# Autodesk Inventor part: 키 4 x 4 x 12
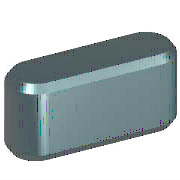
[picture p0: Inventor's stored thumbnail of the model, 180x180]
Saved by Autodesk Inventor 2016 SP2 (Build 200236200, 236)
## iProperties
IsCustomPart: 1
Created: 2012-02
Part Number: 키 4 x 4 x 12
Material: 강철, 연강
Description: 키 및 해당 키홈
Document SubType Name: Modeling
Standard: KS B 1311
Designer: mduedu
Standards Organization: KS
Language: ko-KR
Size Designation: 4 x 4 x 12
Categories: <MemberInstance><Categories><Category DisplayName="샤프트 부품" InternalName="7f7aeb1f-a693-4053-b835-cee3144e0d98" Mnemonic="SHFT"><Category DisplayName="키" Interna
Density: 1 g/cm^3
Appearance: 노란색
Author: mduedu
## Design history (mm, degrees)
workplane "Work Plane1"
workplane "Work Plane2"
sketch "스케치1"
  geometry: L1 (2, 2)-(10, 2); L2 (10, -2)-(2, -2); L3 (0, 9.4)-(0, -7.4) reference; L4 (-5, 0)-(30, 0) reference; L5 (12, 0)-(12, 7); A1 r 2 centre (2, 0) between (2, 2) and (2, -2); A2 r 2 centre (10, 0) between (10, -2) and (10, 2)
  constraints: 6 end point, 5 point on circle, 4 tangent, 3 point on line, 2 centre point, 1 horizontal, 1 parallel, 1 perpendicular
  dimensions: "d0" = 2 radius of A1 (= 0.5 x PB); "d13" = 2 radius of A2 (= 0.5 x PB); "d14" = 12 distance between parallel lines of L5 L3 (= NLG)
extrude "본체1" new body sketch "스케치1" taper "d3" = 0 deg; stored distance "d4" = 10
workplane "Work Plane3"
body "Solid1"
chamfer "모따기1" distance "d8" = 0.25 (= PHH); stored, may be unused: second distance "d9" = 0.25 (= PHH), angle "d15" = 45 deg
other parameters: "d1" = -2.5 (= -PNT), "d2" = 1.5 (= PH - PNT), "NLG" = 12 [user parameter; used in 3 equation terms], "PB" = 4 [user parameter; used in 2 equation terms], "PNT" = 2.5 [user parameter; used in 2 equation terms], "PH" = 4 [user parameter; used in 1 equation term], "PHH" = 0.25 [user parameter; used in 2 equation terms], "d10" = 0, "d16" = 0, "d17" = 0, "d18" = 0, "PLB2" = 12 (= NLG) [user parameter], "WDMAX" = 12 [user parameter], "PLB1" = 12 (= NLG) [user parameter], "RR" = 0.08 [user parameter], "PUEB" = 1.8 [user parameter]
